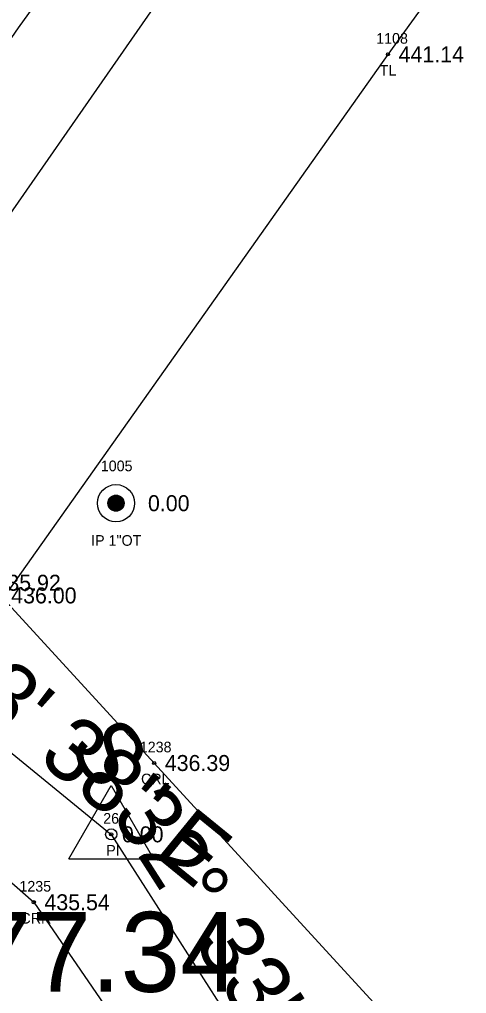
# Model space of a CAD drawing. Extents: x 1762456 to 1764480, y 822234 to 826541.
# Drawn here: x 1763508.9 to 1763550.9, y 824767.8 to 824859.3 of the extents above; entities that cross this region are included whole.
import ezdxf

# ---------------------------------------------------------------- set-up
doc = ezdxf.new("R2010")
doc.units = 0
for name, color, linetype in [('RD_EX_DV_Prop_txCode', 7, 'Continuous'), ('RD_EX_DV_PropPin', 7, 'Continuous'), ('RD_EX_H2O', 7, 'Continuous'), ('RD_EX_H2O_txCode', 7, 'Continuous'), ('RD_EX_Road', 7, 'Continuous'), ('RD_EX_TX_DV_Prop_ELEV', 7, 'Continuous'), ('RD_EX_TX_H2O_ELEV', 7, 'Continuous'), ('RD_EX_TX_VEG_ELEV', 7, 'Continuous'), ('RD_EX_VEG', 7, 'Continuous'), ('RD_EX_VEG_txCode', 7, 'Continuous'), ('RD_HC_Cl', 7, 'Continuous'), ('RD_HC_Data', 7, 'Continuous'), ('RD_HC_Survey_ELEV', 7, 'Continuous'), ('RD_HC_txCode', 7, 'Continuous'), ('RD_SMD_Locator', 7, 'Continuous')]:
    doc.layers.add(name, color=color, linetype=linetype)

msp = doc.modelspace()

# ---------------------------------------------------------------- linework, layer by layer
at = {"layer": 'RD_EX_DV_PropPin'}
for p, q in [((1763517.403, 824813.413), (1763517.403, 824814.361)), ((1763517.438, 824813.372), (1763517.438, 824814.402)), ((1763517.473, 824813.336), (1763517.473, 824814.438)), ((1763517.508, 824813.305), (1763517.508, 824814.469)), ((1763517.543, 824813.277), (1763517.543, 824814.497)), ((1763517.578, 824813.252), (1763517.578, 824814.521)), ((1763517.613, 824813.23), (1763517.613, 824814.543)), ((1763517.648, 824813.211), (1763517.648, 824814.562)), ((1763517.683, 824813.194), (1763517.683, 824814.58)), ((1763517.718, 824813.179), (1763517.718, 824814.594)), ((1763517.753, 824813.166), (1763517.753, 824814.607)), ((1763517.788, 824813.155), (1763517.788, 824814.618)), ((1763517.824, 824813.146), (1763517.824, 824814.627)), ((1763517.859, 824813.139), (1763517.859, 824814.635)), ((1763517.894, 824813.133), (1763517.894, 824814.641)), ((1763517.929, 824813.129), (1763517.929, 824814.645)), ((1763517.964, 824813.127), (1763517.964, 824814.647)), ((1763517.999, 824813.126), (1763517.999, 824814.648)), ((1763518.034, 824813.127), (1763518.034, 824814.647)), ((1763518.069, 824813.129), (1763518.069, 824814.645)), ((1763518.104, 824813.133), (1763518.104, 824814.641)), ((1763518.139, 824813.139), (1763518.139, 824814.635)), ((1763518.174, 824813.146), (1763518.174, 824814.627)), ((1763518.209, 824813.155), (1763518.209, 824814.618)), ((1763518.244, 824813.166), (1763518.244, 824814.607)), ((1763518.279, 824813.179), (1763518.279, 824814.594)), ((1763518.314, 824813.194), (1763518.314, 824814.58)), ((1763518.349, 824813.211), (1763518.349, 824814.562)), ((1763518.384, 824813.23), (1763518.384, 824814.543)), ((1763518.419, 824813.252), (1763518.419, 824814.521)), ((1763518.454, 824813.277), (1763518.454, 824814.497)), ((1763518.489, 824813.305), (1763518.489, 824814.469)), ((1763518.524, 824813.336), (1763518.524, 824814.438)), ((1763518.559, 824813.372), (1763518.559, 824814.402)), ((1763518.594, 824813.413), (1763518.594, 824814.361)), ((1763517.263, 824813.691), (1763517.263, 824814.083)), ((1763517.298, 824813.589), (1763517.298, 824814.185)), ((1763517.333, 824813.517), (1763517.333, 824814.256)), ((1763517.368, 824813.46), (1763517.368, 824814.313)), ((1763518.629, 824813.46), (1763518.629, 824814.313)), ((1763518.664, 824813.517), (1763518.664, 824814.256)), ((1763518.699, 824813.589), (1763518.699, 824814.185)), ((1763518.734, 824813.691), (1763518.734, 824814.083))]:
    msp.add_line(p, q, dxfattribs=at)
for radius in [1.75, 0.761]:
    msp.add_circle((1763517.999, 824813.887), radius, dxfattribs=at)
at = {"layer": 'RD_EX_H2O'}
for points in [[(1763496.792, 824812.847), (1763505.685, 824806.416), (1763507.164, 824805.227), (1763521.579, 824789.488), (1763543.544, 824765.508), (1763572.145, 824752.095), (1763662.415, 824704.478), (1763697.558, 824670.472), (1763707.927, 824630.757), (1763723.525, 824595.874), (1763766.818, 824582.67), (1763818.294, 824585.487), (1763920.084, 824604.11)], [(1763485.591, 824798.12), (1763510.281, 824776.411), (1763530.733, 824746.573), (1763546.507, 824728.759), (1763647.946, 824677.163), (1763661.458, 824680.215), (1763679.149, 824659.291), (1763688.377, 824626.339), (1763689.04, 824599.45), (1763710.73, 824574.271), (1763740.297, 824562.002), (1763762.69, 824555.256), (1763820.302, 824563.648), (1763926.687, 824582.302)]]:
    msp.add_lwpolyline(points, dxfattribs=at)
at = {"layer": 'RD_EX_Road'}
msp.add_lwpolyline([(1763963.891, 825353.592), (1763895.682, 825279.081), (1763827.34, 825205.219), (1763758.38, 825131.335), (1763689.427, 825057.327), (1763653.535, 825018.753), (1763637.74, 825000.803), (1763620.709, 824983.807), (1763588.782, 824946.603), (1763557.13, 824907.379), (1763526.523, 824867.674), (1763498.427, 824827.249)], dxfattribs=at)
at = {"layer": 'RD_EX_VEG'}
msp.add_lwpolyline([(1763654.174, 824981.39), (1763637.841, 824967.614), (1763603.039, 824934.549), (1763572.899, 824896.618), (1763543.523, 824856.037), (1763489.474, 824779.675), (1763459.285, 824736.58), (1763444.879, 824693.265), (1763423.623, 824647.114), (1763401.17, 824604.963), (1763396.878, 824581.151)], dxfattribs=at)
at = {"layer": 'RD_HC_Cl'}
for p, q in [((1763490.817, 824804.588), (1763517.555, 824782.789)), ((1763517.555, 824782.789), (1763536.928, 824752.455))]:
    msp.add_line(p, q, dxfattribs=at)
msp.add_arc((1764677.021, 824029.626), 1432.392, 137.053176, 159.117629, dxfattribs=at)
at = {"layer": 'RD_HC_Data'}
for p, q in [((1763513.584, 824780.496), (1763517.556, 824787.376)), ((1763517.556, 824787.376), (1763521.525, 824780.496)), ((1763513.584, 824780.496), (1763521.525, 824780.496))]:
    msp.add_line(p, q, dxfattribs=at)
msp.add_circle((1763517.555, 824782.789), 0.529, dxfattribs=at)
at = {"layer": 'RD_SMD_Locator'}
for centre in [(1763543.523, 824856.037), (1763517.999, 824813.887), (1763521.579, 824789.488), (1763517.555, 824782.789), (1763510.281, 824776.411)]:
    msp.add_circle(centre, 0.15, dxfattribs=at)

# ---------------------------------------------------------------- texts
at = {"layer": 'RD_EX_DV_Prop_txCode'}
for s, p in [('1005', (1763516.573, 824816.887)), ('IP 1"OT', (1763515.668, 824809.887))]:
    msp.add_text(s, height=1, dxfattribs=at).set_placement(p)
at = {"layer": 'RD_EX_H2O_txCode'}
for s, p in [('1238', (1763520.233, 824790.488)), ('CRL', (1763520.351, 824787.488)), ('1235', (1763508.935, 824777.411)), ('CRR', (1763509.029, 824774.411))]:
    msp.add_text(s, height=1, dxfattribs=at).set_placement(p)
at = {"layer": 'RD_EX_TX_DV_Prop_ELEV'}
msp.add_text('0.00', height=1.5, dxfattribs=at).set_placement((1763520.999, 824813.137))
at = {"layer": 'RD_EX_TX_H2O_ELEV'}
for s, p in [('435.92', (1763506.685, 824805.666)), ('436.00', (1763508.164, 824804.477)), ('436.39', (1763522.579, 824788.738)), ('435.54', (1763511.281, 824775.661))]:
    msp.add_text(s, height=1.5, dxfattribs=at).set_placement(p)
at = {"layer": 'RD_EX_TX_VEG_ELEV'}
msp.add_text('441.14', height=1.5, dxfattribs=at).set_placement((1763544.523, 824855.287))
at = {"layer": 'RD_EX_VEG_txCode'}
for s, p in [('1108', (1763542.421, 824857.037)), ('TL', (1763542.752, 824854.037))]:
    msp.add_text(s, height=1, dxfattribs=at).set_placement(p)
at = {"layer": 'RD_HC_Data'}
for s, rotation, p in [('S 50%%d 48\' 38" E', 320.81043, (1763483.703, 824811.678)), ('S 32%%d 33\' 51" E', 302.56412, (1763513.421, 824791.12))]:
    msp.add_text(s, height=6, rotation=rotation, dxfattribs=at).set_placement(p)
msp.add_text('P.I. = 45+77.34', height=7.5, dxfattribs=at).set_placement((1763461, 824768))
at = {"layer": 'RD_HC_Survey_ELEV'}
msp.add_text('0.00', height=1.5, dxfattribs=at).set_placement((1763518.555, 824782.039))
at = {"layer": 'RD_HC_txCode'}
for s, p in [('26', (1763516.799, 824783.789)), ('PI', (1763517.083, 824780.789))]:
    msp.add_text(s, height=1, dxfattribs=at).set_placement(p)

doc.saveas('drawing.dxf')
